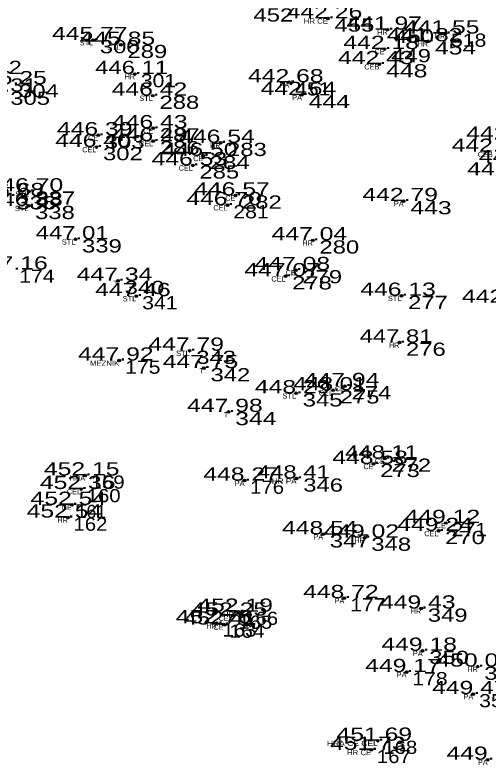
# Model space of a CAD drawing. Extents: x -639390 to -639074, y -1138747 to -1138358.
# Drawn here: x -639228.46 to -639201.57, y -1138684.31 to -1138641.7 of the extents above; entities that cross this region are included whole.
import ezdxf
from ezdxf.enums import TextEntityAlignment as Align

# ---------------------------------------------------------------- set-up
doc = ezdxf.new("R2010")
doc.units = 0
doc.header["$LTSCALE"] = 0.3
doc.header["$PDMODE"] = 32
doc.header["$PDSIZE"] = 0.15
for name, color, linetype in [('11', 7, 'Continuous'), ('12', 7, 'Continuous'), ('13', 7, 'Continuous'), ('57', 7, 'Continuous')]:
    doc.layers.add(name, color=color, linetype=linetype)

msp = doc.modelspace()

# ---------------------------------------------------------------- linework, layer by layer
at = {"layer": '11'}
for p in [(-639210.67, -1138641.89), (-639207.28, -1138642.53), (-639204.01, -1138642.75), (-639224.01, -1138643.12), (-639204.98, -1138643.19), (-639222.44, -1138643.39), (-639207.45, -1138643.63), (-639207.75, -1138644.49), (-639221.64, -1138645.05), (-639212.87, -1138645.52), (-639220.62, -1138646.28), (-639212.15, -1138646.24), (-639220.6, -1138648.13), (-639223.73, -1138648.53), (-639220.6, -1138648.86), (-639216.78, -1138648.96), (-639223.83, -1138649.2), (-639217.76, -1138649.7), (-639218.35, -1138650.24), (-639227.67, -1138651.72), (-639215.93, -1138651.95), (-639227.69, -1138652.54), (-639216.38, -1138652.5), (-639206.37, -1138652.27), (-639225.02, -1138654.44), (-639211.53, -1138654.5), (-639212.5, -1138656.19), (-639222.6, -1138656.8), (-639213.08, -1138656.54), (-639221.56, -1138657.67), (-639206.49, -1138657.65), (-639206.61, -1138660.31), (-639218.53, -1138660.77), (-639222.53, -1138661.33), (-639217.72, -1138661.76), (-639209.7, -1138662.78), (-639212.48, -1138663.19), (-639210.38, -1138663.02), (-639216.33, -1138664.25), (-639207.44, -1138666.9), (-639208.08, -1138667.2), (-639224.47, -1138667.86), (-639215.41, -1138668.15), (-639212.45, -1138668.03), (-639224.7, -1138668.63), (-639225.23, -1138669.53), (-639225.45, -1138670.25), (-639203.97, -1138670.56), (-639210.94, -1138671.2), (-639204.39, -1138671.01), (-639208.58, -1138671.39), (-639209.74, -1138674.83), (-639215.75, -1138675.6), (-639205.37, -1138675.42), (-639216.08, -1138675.82), (-639216.98, -1138676.26), (-639216.61, -1138676.33), (-639205.29, -1138677.82), (-639202.16, -1138678.72), (-639206.21, -1138679.03), (-639202.41, -1138680.28), (-639207.84, -1138682.93), (-639208.21, -1138683.45), (-639201.59, -1138684.01)]:
    msp.add_point(p, dxfattribs=at)

# ---------------------------------------------------------------- texts
at = {"layer": '12'}
for s, width, p in [('442.26 ', 1.4, (-639210.669, -1138641.89)), ('441.97 ', 1.4, (-639207.28, -1138642.53)), ('441.55 ', 1.4, (-639204.01, -1138642.75)), ('445.77 ', 1.4, (-639224.01, -1138643.12)), ('445.85 ', 1.4, (-639222.44, -1138643.39)), ('441.82 ', 1.4, (-639204.98, -1138643.19)), ('442.18 ', 1.4, (-639207.45, -1138643.63)), ('442.43 ', 1.4, (-639207.75, -1138644.49)), ('446.11 ', 1.35, (-639221.639, -1138645.05)), ('442.68 ', 1.4, (-639212.87, -1138645.52)), ('446.25 ', 1.4, (-639228.6, -1138645.63)), ('446.31 ', 1.35, (-639229.099, -1138646.05)), ('446.42 ', 1.4, (-639220.62, -1138646.28)), ('442.64 ', 1.4, (-639212.15, -1138646.24)), ('446.43 ', 1.4, (-639220.6, -1138648.13)), ('446.39 ', 1.4, (-639223.73, -1138648.53)), ('446.49 ', 1.4, (-639220.6, -1138648.86)), ('446.54 ', 1.4, (-639216.78, -1138648.96)), ('442.10 ', 1.4, (-639200.47, -1138648.78)), ('446.40 ', 1.4, (-639223.83, -1138649.2)), ('446.50 ', 1.4, (-639217.76, -1138649.7)), ('442.16 ', 1.4, (-639201.299, -1138649.47)), ('446.53 ', 1.4, (-639218.35, -1138650.24)), ('442.20 ', 1.4, (-639199.75, -1138650.11)), ('442.18 ', 1.4, (-639200.41, -1138650.81)), ('446.68 ', 1.4, (-639228.75, -1138651.99)), ('446.70 ', 1.4, (-639227.67, -1138651.72)), ('446.57 ', 1.4, (-639215.93, -1138651.95)), ('442.79 ', 1.4, (-639206.37, -1138652.27)), ('446.88 ', 1.4, (-639227.69, -1138652.54)), ('446.70 ', 1.4, (-639216.38, -1138652.5)), ('447.01 ', 1.35, (-639225.019, -1138654.44)), ('447.04 ', 1.4, (-639211.53, -1138654.5)), ('447.16 ', 1.4, (-639228.549, -1138656.16)), ('447.08 ', 1.4, (-639212.5, -1138656.19)), ('447.07 ', 1.4, (-639213.08, -1138656.54)), ('447.34 ', 1.4, (-639222.6, -1138656.8)), ('447.46 ', 1.4, (-639221.559, -1138657.67)), ('446.13 ', 1.4, (-639206.49, -1138657.65)), ('442.94 ', 1.4, (-639200.71, -1138658.05)), ('447.81 ', 1.35, (-639206.609, -1138660.31)), ('447.79 ', 1.4, (-639218.53, -1138660.77)), ('447.92 ', 1.4, (-639222.53, -1138661.33)), ('447.75 ', 1.4, (-639217.72, -1138661.76)), ('448.01 ', 1.35, (-639210.379, -1138663.02)), ('447.94 ', 1.4, (-639209.7, -1138662.78)), ('448.29 ', 1.4, (-639212.48, -1138663.19)), ('447.98 ', 1.4, (-639216.33, -1138664.25)), ('448.11 ', 1.35, (-639207.439, -1138666.9)), ('448.58 ', 1.4, (-639208.08, -1138667.2)), ('452.15 ', 1.4, (-639224.47, -1138667.86)), ('448.27 ', 1.4, (-639215.41, -1138668.15)), ('448.41 ', 1.35, (-639212.449, -1138668.03)), ('452.36 ', 1.4, (-639224.699, -1138668.63)), ('452.54 ', 1.4, (-639225.23, -1138669.53)), ('452.54 ', 1.4, (-639225.45, -1138670.25)), ('449.12 ', 1.4, (-639203.97, -1138670.56)), ('449.24 ', 1.4, (-639204.39, -1138671.01)), ('448.54 ', 1.4, (-639210.94, -1138671.2)), ('449.02 ', 1.4, (-639208.58, -1138671.39)), ('448.72 ', 1.4, (-639209.74, -1138674.83)), ('449.43 ', 1.4, (-639205.37, -1138675.42)), ('452.25 ', 1.4, (-639216.08, -1138675.82)), ('452.19 ', 1.4, (-639215.75, -1138675.6)), ('452.76 ', 1.4, (-639216.979, -1138676.26)), ('452.41 ', 1.35, (-639216.609, -1138676.33)), ('449.18 ', 1.4, (-639205.29, -1138677.82)), ('450.00 ', 1.4, (-639202.16, -1138678.72)), ('449.17 ', 1.4, (-639206.21, -1138679.03)), ('449.47 ', 1.4, (-639202.41, -1138680.28)), ('451.69 ', 1.4, (-639207.84, -1138682.93)), ('451.73 ', 1.4, (-639208.21, -1138683.45)), ('449.69 ', 1.4, (-639201.59, -1138684.01))]:
    msp.add_text(s, height=0.75, dxfattribs=dict(at, width=width)).set_placement(p, align=Align.CENTER)
at = {"layer": '13'}
for s, width, p in [(' 452', 1.35, (-639215.28, -1138642.07)), (' 455', 1.35, (-639210.67, -1138642.64)), (' 450', 1.35, (-639207.28, -1138643.28)), (' 300', 1.35, (-639224.01, -1138643.87)), (' 518', 1.2, (-639204.01, -1138643.5)), (' 289', 1.35, (-639222.44, -1138644.14)), (' 454', 1.4, (-639204.98, -1138643.94)), (' 449', 1.35, (-639207.45, -1138644.38)), (' 322', 1.35, (-639230.7, -1138645.05)), (' 448', 1.4, (-639207.75, -1138645.24)), (' 301', 1.2, (-639221.64, -1138645.8)), (' 304', 1.35, (-639228.6, -1138646.38)), (' 451', 1.2, (-639212.87, -1138646.27)), (' 305', 1.35, (-639229.1, -1138646.8)), (' 288', 1.35, (-639220.62, -1138647.03)), (' 444', 1.4, (-639212.15, -1138646.99)), (' 287', 1.35, (-639220.6, -1138648.88)), (' 303', 1.35, (-639223.73, -1138649.28)), (' 286', 1.35, (-639220.6, -1138649.61)), (' 283', 1.35, (-639216.78, -1138649.71)), (' 302', 1.35, (-639223.83, -1138649.95)), (' 284', 1.35, (-639217.76, -1138650.45)), (' 285', 1.35, (-639218.35, -1138650.99)), (' 336', 1.35, (-639228.75, -1138652.74)), (' 337', 1.35, (-639227.67, -1138652.47)), (' 282', 1.35, (-639215.93, -1138652.7)), (' 338', 1.35, (-639227.69, -1138653.29)), (' 281', 1.2, (-639216.38, -1138653.25)), (' 443', 1.4, (-639206.37, -1138653.02)), (' 339', 1.35, (-639225.02, -1138655.19)), (' 280', 1.35, (-639211.53, -1138655.25)), (' 174', 1.2, (-639228.55, -1138656.91)), (' 279', 1.35, (-639212.5, -1138656.94)), (' 340', 1.35, (-639222.6, -1138657.55)), (' 278', 1.35, (-639213.08, -1138657.29)), (' 277', 1.35, (-639206.49, -1138658.4)), (' 341', 1.2, (-639221.56, -1138658.42)), (' 276', 1.35, (-639206.61, -1138661.06)), (' 343', 1.35, (-639218.53, -1138661.52)), (' 175', 1.2, (-639222.53, -1138662.08)), (' 342', 1.35, (-639217.72, -1138662.51)), (' 345', 1.35, (-639212.48, -1138663.94)), (' 275', 1.35, (-639210.38, -1138663.77)), (' 274', 1.35, (-639209.7, -1138663.53)), (' 344', 1.4, (-639216.33, -1138665)), (' 272', 1.35, (-639207.44, -1138667.65)), (' 273', 1.35, (-639208.08, -1138667.95)), (' 159', 1.15, (-639224.47, -1138668.61)), (' 176', 1.15, (-639215.41, -1138668.9)), (' 346', 1.35, (-639212.45, -1138668.78)), (' 160', 1.15, (-639224.7, -1138669.38)), (' 162', 1.15, (-639225.45, -1138671)), (' 271', 1.2, (-639203.97, -1138671.31)), (' 347', 1.35, (-639210.94, -1138671.95)), (' 270', 1.35, (-639204.39, -1138671.76)), (' 348', 1.35, (-639208.58, -1138672.14)), (' 177', 1.2, (-639209.74, -1138675.58)), (' 349', 1.35, (-639205.37, -1138676.17)), (' 165', 1.15, (-639216.08, -1138676.57)), (' 166', 1.15, (-639215.75, -1138676.35)), (' 163', 1.15, (-639216.98, -1138677.01)), (' 164', 1.2, (-639216.61, -1138677.08)), (' 350', 1.35, (-639205.29, -1138678.57)), (' 352', 1.35, (-639202.16, -1138679.47)), (' 178', 1.2, (-639206.21, -1138679.78)), (' 351', 1.2, (-639202.41, -1138681.03)), (' 168', 1.15, (-639207.84, -1138683.68)), (' 167', 1.15, (-639208.21, -1138684.2))]:
    msp.add_text(s, height=0.75, dxfattribs=dict(at, width=width)).set_placement(p)
msp.add_text(' 161', height=0.75, dxfattribs=at).set_placement((-639225.23, -1138670.28))
at = {"layer": '57'}
for s, width, p in [('HR CE', 1.1, (-639210.67, -1138642.19)), ('HR', 0.85, (-639207.279, -1138642.83)), ('STL', 1.05, (-639224.009, -1138643.42)), ('HR', 0.85, (-639204.009, -1138643.05)), ('STL', 1.05, (-639222.439, -1138643.69)), ('HR', 0.85, (-639204.979, -1138643.49)), ('CE', 0.9, (-639207.45, -1138643.93)), ('HR', 0.85, (-639221.639, -1138645.35)), ('PA', 0.95, (-639212.87, -1138645.82)), ('STL', 1.05, (-639220.619, -1138646.58)), ('PA', 0.95, (-639212.15, -1138646.54)), ('CE', 0.9, (-639220.6, -1138648.43)), ('CE', 0.9, (-639223.73, -1138648.83)), ('HR', 0.85, (-639216.779, -1138649.26)), ('CE', 0.9, (-639217.76, -1138650)), ('STL', 1.05, (-639227.669, -1138652.02)), ('CE', 0.9, (-639215.93, -1138652.25)), ('PA', 0.95, (-639206.37, -1138652.57)), ('STL', 1.05, (-639227.689, -1138652.84)), ('STL', 1.05, (-639225.019, -1138654.74)), ('HR', 0.85, (-639211.529, -1138654.8)), ('CE', 0.9, (-639212.5, -1138656.49)), ('T', 0.85, (-639222.6, -1138657.1)), ('STL', 1.05, (-639221.559, -1138657.97)), ('STL', 1.05, (-639206.489, -1138657.95)), ('HR', 0.85, (-639206.609, -1138660.61)), ('STL', 1.05, (-639218.529, -1138661.07)), ('MEZNIK', 1.1, (-639222.529, -1138661.63)), ('T', 0.85, (-639217.72, -1138662.06)), ('CE', 0.9, (-639209.7, -1138663.08)), ('STL', 1.05, (-639212.479, -1138663.49)), ('T', 0.85, (-639216.33, -1138664.55)), ('CE', 0.9, (-639207.44, -1138667.2)), ('CE', 0.9, (-639208.08, -1138667.5)), ('HRA', 0.95, (-639224.47, -1138668.16)), ('PA', 0.95, (-639215.41, -1138668.45)), ('HR PA', 1.15, (-639212.45, -1138668.33)), ('CE', 0.9, (-639225.23, -1138669.83)), ('HR', 0.85, (-639225.449, -1138670.55)), ('CE', 0.9, (-639203.97, -1138670.86)), ('PA', 0.95, (-639210.94, -1138671.5)), ('HR', 0.85, (-639208.579, -1138671.69)), ('PA', 0.95, (-639209.74, -1138675.13)), ('HR', 0.85, (-639205.369, -1138675.72)), ('HRA', 0.95, (-639215.75, -1138675.9)), ('HR', 0.85, (-639216.979, -1138676.56)), ('CE', 0.9, (-639216.61, -1138676.63)), ('PA', 0.95, (-639205.29, -1138678.12)), ('HR', 0.85, (-639202.159, -1138679.02)), ('PA', 0.95, (-639206.21, -1138679.33)), ('PA', 0.95, (-639202.41, -1138680.58)), ('HRA CE CEL', 1.2, (-639207.839, -1138683.23)), ('HR CE', 1.1, (-639208.21, -1138683.75)), ('PA', 0.95, (-639201.59, -1138684.31))]:
    msp.add_text(s, height=0.3, dxfattribs=dict(at, width=width)).set_placement(p, align=Align.RIGHT)
for s, p in [('CEB', (-639207.749, -1138644.79)), ('CEL', (-639220.599, -1138649.16)), ('CEL', (-639223.829, -1138649.5)), ('CEB', (-639201.299, -1138649.77)), ('CEL', (-639218.349, -1138650.54)), ('CEL', (-639216.379, -1138652.8)), ('CEL', (-639213.079, -1138656.84)), ('CEL', (-639210.379, -1138663.32)), ('CEL', (-639224.699, -1138668.93)), ('CEL', (-639204.389, -1138671.31)), ('CEL', (-639216.079, -1138676.12))]:
    msp.add_text(s, height=0.3, dxfattribs=at).set_placement(p, align=Align.RIGHT)

doc.saveas('drawing.dxf')
